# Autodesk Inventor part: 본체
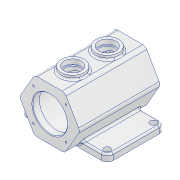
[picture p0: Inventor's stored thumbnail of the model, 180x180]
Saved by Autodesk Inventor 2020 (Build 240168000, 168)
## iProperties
Created: 2021-06
Part Number: 본체
Material: 알루미늄 6061
Document SubType Name: Modeling
Designer: MIRAE
Mass: 1495.74 g
Surface Area: 1102.11 cm^2
Volume: 553.979 cm^3
Density: 2.7 g/cm^3
Appearance: 알루미늄 - 평지
Author: MIRAE
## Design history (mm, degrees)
sketch "스케치1"
  geometry: L1 (26.25, 45.466)-(52.5, 0); L2 (52.5, 0)-(26.25, -45.466); L3 (26.25, -45.466)-(-26.25, -45.466); L4 (-26.25, -45.466)-(-52.5, 0); L5 (-52.5, 0)-(-26.25, 45.466); L6 (-26.25, 45.466)-(26.25, 45.466); 2 further points
  constraints: 12 end point, 1 coincident, 1 horizontal, 13 other
  dimensions: "d0" = 105 distance of L1.end L4.end
extrude "돌출1" new body sketch "스케치1" stored distance "d2" = 140; taper "d3" = 0 deg
sketch "스케치2"
  geometry: C1 r 30 at (0, 0); 1 further point
  constraints: 1 centre point, 1 coincident
  dimensions: "d4" = 60 diameter of C1
extrude "돌출2" cut sketch "스케치2" extent not by distance; stored distance "d5" = 0; taper "d6" = 0 deg
sketch "스케치3"
  geometry: C1 r 30 at (0, 0) reference; C2 r 37.5 at (0, 0); 1 further point
  constraints: 1 centre point, 1 coincident
  dimensions: "d7" = 75 diameter of C2
extrude "돌출3" cut sketch "스케치3" stored distance "d8" = 116; taper "d9" = 0 deg
node "작업 평면1"
sketch "스케치4"
  geometry: L1 (-75, 45)-(75, 45); L2 (75, 45)-(75, -55); L3 (75, -55)-(-75, -55); L4 (-75, -55)-(-75, 45); L5 (-75, 45)-(75, -55); L6 (75, 45)-(-75, -55); L7 (26.25, 70)-(52.5, 70) reference; L8 (26.25, -70)-(-26.25, -70) reference; 2 further points
  constraints: 12 end point, 2 midpoint, 1 parallel, 1 other
  dimensions: "d11" = 100 distance of L1.end L2.end; "d12" = 150 distance of L2.end L3.end; "d88" = 25 distance between parallel lines of L7 L1; "d89" = 15 distance between parallel lines of L8 L3; "d90" = 75 distance from line of point (0, 0) L2
extrude "돌출4" join sketch "스케치4" distance "d13" = 12; taper "d14" = 0 deg
node "작업 평면2"
sketch "스케치7"
  geometry: L1 (-26.25, 70)-(26.25, 70) reference; C1 r 20 at (0, 30); C2 r 20 at (0, -30); 1 further point
  constraints: 2 centre point, 2 vertical alignment
  dimensions: "d29" = 40 diameter of C1; "d30" = 40 diameter of C2; "d31" = 40 distance from line of L1 C1.centre; "d32" = 60 distance of C2.centre C1.centre
extrude "돌출6" join sketch "스케치7" stored distance "d33" = 5; taper "d34" = 0 deg
sketch "스케치8"
  geometry: C1 r 20 at (0, 0) reference; C2 r 20 at (0, 60) reference; 3 further points
  constraints: 2 coincident
hole "구멍2" sketch "스케치8" at (0, 0), (0, 60) diameter "d35" = 25; stored, may be unused: countersink angle "d39" = 90 deg, drill point angle "d41" = 0 deg; dims "d36" = 6, "d37" = 30, "d38" = 8, "d40" = 30
sketch "스케치9"
  geometry: L1 (30.561, -45)-(75, -45) reference; L2 (75, -45)-(75, 55) reference; C1 r 5.5 at (65, -35); 1 further point
  constraints: 1 centre point
  dimensions: "d42" = 11 diameter of C1; "d91" = 10 distance from line of C1.centre L1
extrude "돌출7" cut sketch "스케치9" extent not by distance; stored distance "d45" = 0; taper "d46" = 0 deg
sketch "스케치11"
  geometry: L1 (0, 0)-(0, 52.5); L2 (-15, 52.5)-(15, 52.5) reference; L3 (0, 0)-(-28.284, 28.284); 1 further point
  constraints: 4 end point, 1 coincident, 1 midpoint
  dimensions: "d55" = 40 distance of L1.start L3.end; "d56" = 45 deg angle of L1 L3
hole "구멍3" sketch "스케치11" at (-28.284, 28.284) diameter "d47" = 3.242; stored, may be unused: countersink angle "d51" = 90 deg, drill point angle "d53" = 120 deg; dims "d48" = 8, "d49" = 30, "d50" = 8, "d52" = 10
sketch "스케치13"
  geometry: 2 further points
  constraints: 1 vertical alignment
  dimensions: "d67" = 40 distance of point (0, 0) point (0, 40)
hole "구멍4" sketch "스케치13" at (0, 40) diameter "d60" = 3.242; stored, may be unused: countersink angle "d64" = 90 deg, drill point angle "d66" = 120 deg; dims "d61" = 8, "d62" = 30, "d63" = 8, "d65" = 10
fillet "모깎기1" dims "d71" = 10
fillet "모깎기2" dims "d72" = 8
fillet "모깎기3" dims "d73" = 8
fillet "모깎기4" dims "d77" = 3
chamfer "모따기2" distance "d78" = 1; stored, may be unused: second distance "d79" = 2, angle "d80" = 45 deg
fillet "모깎기5" dims "d81" = 5
fillet "모깎기6" dims "d82" = 3
fillet "모깎기7" dims "d83" = 3
sketch "스케치14"
  geometry: L1 (-75, 45)-(-75, -35) reference; L2 (-65, -45)-(-32.293, -45) reference; 2 further points
  constraints: 1 other
  dimensions: "d84" = 14 distance from line of L1 point (-61, 5); "d85" = 50 distance from line of L2 point (-61, 5)
feature "엠보싱1" sketch "스케치14" dims "d0" = 105, "d86" = 0.5, "d87" = 0
sketch "스케치15"
  geometry: A1 r 7 centre (65, 45) between (72, 45) and (65, 52) reference; 2 further points
  constraints: 1 coincident
hole "구멍5" sketch "스케치15" at (65, 45) diameter "d92" = 11; stored, may be unused: countersink angle "d96" = 90 deg, drill point angle "d98" = 120 deg; dims "d93" = 8, "d94" = 30, "d95" = 8, "d97" = 10
sketch "스케치16"
  geometry: A1 r 10 centre (-65, -35) between (-75, -35) and (-65, -45) reference; 2 further points
  constraints: 1 coincident
hole "구멍6" sketch "스케치16" at (-65, -35) diameter "d99" = 11; stored, may be unused: countersink angle "d103" = 90 deg, drill point angle "d105" = 120 deg; dims "d100" = 8, "d101" = 30, "d102" = 8, "d104" = 10
sketch "스케치17"
  geometry: A1 r 10 centre (-65, 45) between (-65, 55) and (-75, 45) reference; 2 further points
  constraints: 1 coincident
hole "구멍7" sketch "스케치17" at (-65, 45) diameter "d106" = 11; stored, may be unused: countersink angle "d110" = 90 deg, drill point angle "d112" = 120 deg; dims "d107" = 8, "d108" = 30, "d109" = 8, "d111" = 10
chamfer "모따기3" distance "d113" = 1; stored, may be unused: second distance "d114" = 2, angle "d115" = 45 deg
node "솔리드1"
pattern_circular "원형 패턴1" dims angle "d58" = 360 deg
pattern_circular "원형 패턴2" dims angle "d69" = 360 deg
feature "A9D066F2-1C7D-4E18-AEED-F7BC21143FA4" dims "d35" = 25, "d36" = 6, "d37" = 30, "d38" = 8, "d39" = 90 deg, "d40" = 30, "d41" = 0
other parameters: "d28" = 52.5
